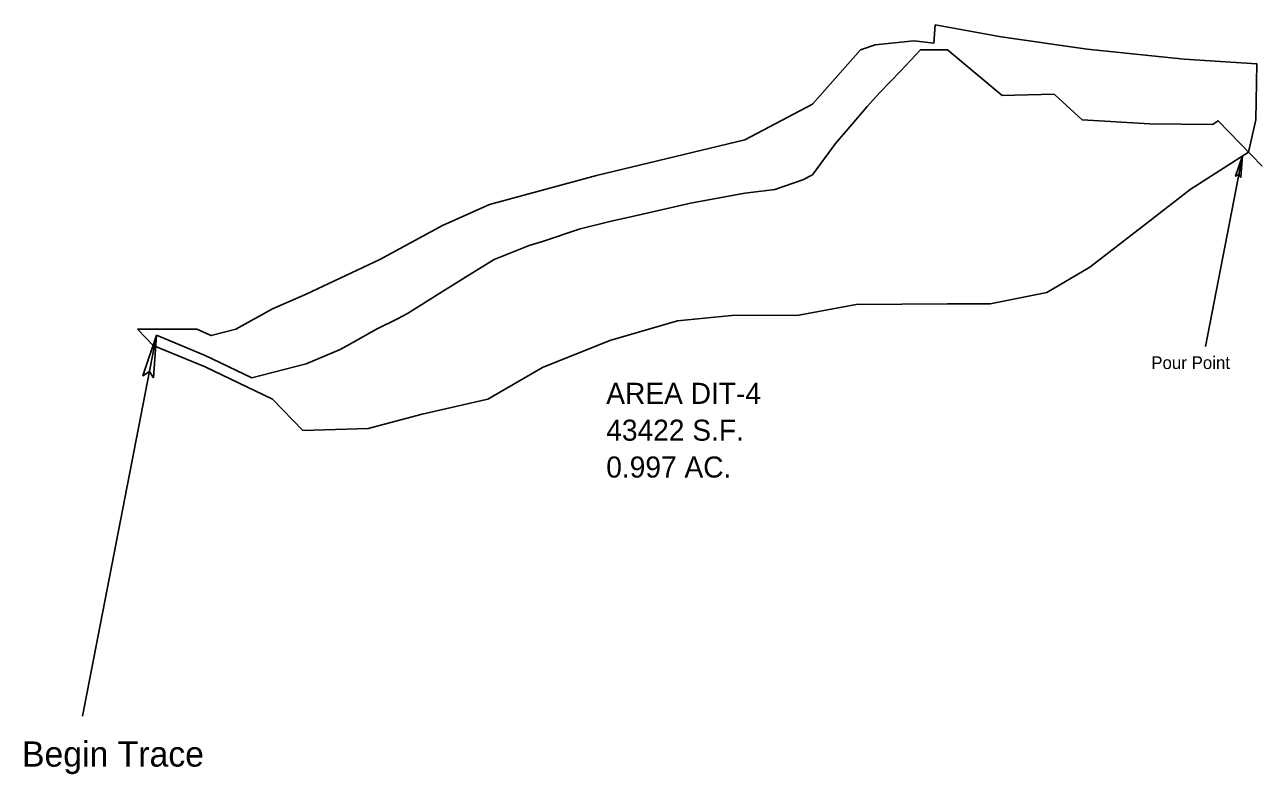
# Model space of a CAD drawing. Extents: x 3307 to 5445, y 2655 to 3371.
import ezdxf

# ---------------------------------------------------------------- set-up
doc = ezdxf.new("R2010")
doc.units = 0
for name, color, linetype in [('Default', 7, 'Continuous'), ('DESIGN - SCRATCH - User 1', 7, 'Continuous'), ('SURVEY - CENTERLINE - Preliminary', 7, 'Continuous'), ('SURVEY - CENTERLINE - Preliminary Text', 7, 'Continuous'), ('SURVEY - DRAINAGE - Area Shapes', 7, 'Continuous')]:
    doc.layers.add(name, color=color, linetype=linetype)

msp = doc.modelspace()

# ---------------------------------------------------------------- linework, layer by layer
at = {"layer": 'Default'}
msp.add_line((3360.7, 2865.94), (3361.69, 2865.94), dxfattribs=at)
at = {"layer": 'DESIGN - SCRATCH - User 1'}
msp.add_line((3885.86, 2948.31), (3868.33, 2857.86), dxfattribs=at)
msp.add_lwpolyline([(3885.86, 2948.31), (3885.18, 2938.2), (3884.2, 2939.72), (3882.68, 2938.69)], close=True, dxfattribs=at)
msp.add_lwpolyline([(3885.86, 2948.31), (3885.18, 2938.2), (3884.2, 2939.72), (3882.68, 2938.69), (3885.86, 2948.31)], dxfattribs=at)
at = {"layer": 'SURVEY - CENTERLINE - Preliminary'}
msp.add_lwpolyline([(3369.59, 2863.1), (3392.78, 2853.57), (3415.03, 2842.91), (3424.85, 2845.47), (3440.74, 2849.5), (3456.93, 2856.28), (3463.04, 2859.62), (3474.27, 2865.94), (3484.25, 2870.87), (3489.01, 2873.42), (3504.41, 2883.19), (3521.08, 2893.57), (3524.43, 2895.67), (3530.21, 2899.13), (3546.8, 2905.71), (3553.16, 2907.67), (3571.12, 2913.74), (3585.24, 2917.14), (3597.26, 2919.88), (3617.32, 2924.51), (3623.57, 2925.85), (3649.39, 2930.6), (3650.81, 2930.85), (3663.59, 2932.32), (3676.98, 2936.96), (3681.47, 2939.33), (3692.4, 2954.2), (3702.05, 2965.51), (3707.45, 2971.81), (3713.55, 2978.43), (3723.33, 2988.57), (3732.89, 2998.69), (3745.62, 2998.69), (3771.67, 2976.96), (3777.7, 2977.24), (3796.35, 2977.69), (3809.78, 2965.51), (3841.85, 2963.53), (3871.74, 2963.24), (3874.44, 2964.98), (3895.32, 2943.37)], dxfattribs=at)
at = {"layer": 'SURVEY - CENTERLINE - Preliminary Text'}
msp.add_line((3369.59, 2863.1), (3334.53, 2682.21), dxfattribs=at)
msp.add_lwpolyline([(3369.59, 2863.1), (3368.22, 2842.9), (3366.26, 2845.92), (3363.22, 2843.87)], close=True, dxfattribs=at)
msp.add_lwpolyline([(3369.59, 2863.1), (3368.22, 2842.9), (3366.26, 2845.92), (3363.22, 2843.87), (3369.59, 2863.1)], dxfattribs=at)
at = {"layer": 'SURVEY - DRAINAGE - Area Shapes'}
for points in [[(3739.81, 3010.61), (3739.26, 3001.94), (3729.7, 3002.97), (3711.24, 3001.08), (3704.31, 2998.69), (3681.47, 2972.96), (3649.39, 2955.98), (3578.76, 2939.02), (3527.95, 2925.21), (3505.56, 2915.19), (3475.9, 2899.13), (3440.83, 2882.6), (3424.85, 2875.6), (3407.31, 2865.94), (3395.69, 2862.93), (3388.83, 2865.94), (3360.7, 2865.94)], [(3360.7, 2865.94), (3368.14, 2858.24), (3392.78, 2848.11), (3424.85, 2832.76), (3439.3, 2817.81), (3470.36, 2818.86), (3495.88, 2825.65), (3527.2, 2832.76), (3553.16, 2847.83), (3585.24, 2860.59), (3617.32, 2869.92), (3643.04, 2872.52), (3674.99, 2872.65), (3702.21, 2877.68), (3745.62, 2878.07), (3765.98, 2878.07), (3792.91, 2883.4), (3813.35, 2895.44), (3841.85, 2917.44), (3861.1, 2932.32), (3888.75, 2950.17), (3892.29, 2965.51), (3892.67, 2992.07), (3858.26, 2994.24), (3812.06, 2998.97), (3771.22, 3004.92), (3739.81, 3010.61)]]:
    msp.add_lwpolyline(points, dxfattribs=at)

# ---------------------------------------------------------------- texts
at = {"layer": 'Default'}
for s, p in [('AREA DIT-4', (3583.47, 2830.53)), ('43422 S.F.', (3583.47, 2813.03)), ('0.997 AC.', (3583.47, 2795.53))]:
    msp.add_text(s, height=10, dxfattribs=at).set_placement(p)
at = {"layer": 'DESIGN - SCRATCH - User 1'}
msp.add_text('Pour Point', height=6, dxfattribs=at).set_placement((3842.55, 2847.09))
at = {"layer": 'SURVEY - CENTERLINE - Preliminary Text'}
msp.add_text('Begin Trace', height=12, dxfattribs=at).set_placement((3305.71, 2658.22))

doc.saveas('drawing.dxf')
